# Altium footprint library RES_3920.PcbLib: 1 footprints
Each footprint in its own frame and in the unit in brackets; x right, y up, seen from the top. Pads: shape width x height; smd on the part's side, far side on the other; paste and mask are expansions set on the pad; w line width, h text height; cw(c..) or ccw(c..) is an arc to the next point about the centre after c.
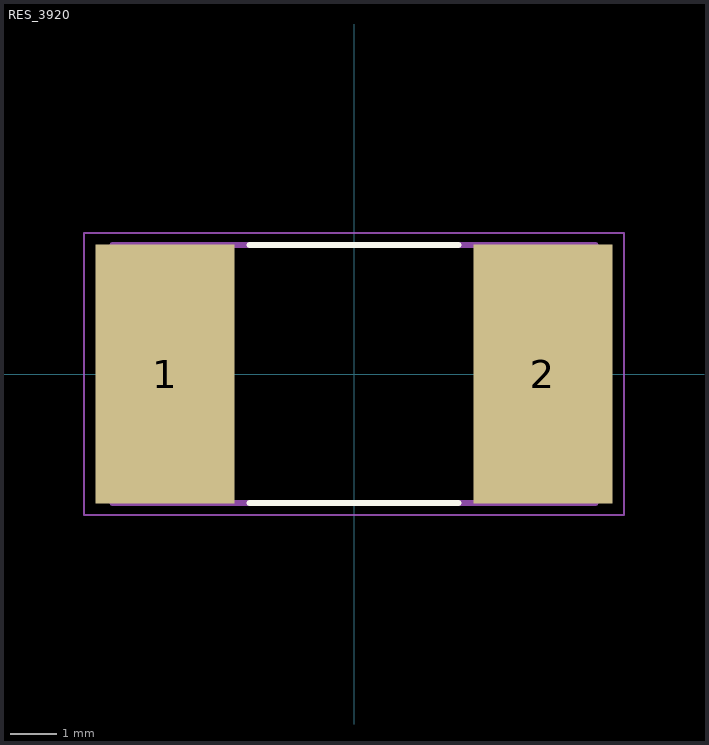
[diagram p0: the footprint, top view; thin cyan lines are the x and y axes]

## RES_3920 [mm]
pads (2):
  rect 2.96x5.51 smd: 1(-4.027,0) 2(4.027,0)
Top Overlay:
  lines w0.127: -2.23,-2.75 2.23,-2.75 ; -2.23,2.75 2.23,2.75
Assembly Top:
  lines w0.127: -5.15,-2.75 -5.15,2.75 5.15,2.75 5.15,-2.75 -5.15,-2.75
Courtyard Top:
  lines w0.05: -5.755,-3.005 -5.755,3.005 5.755,3.005 5.755,-3.005 -5.755,-3.005
3D body "RES_3920.STEP": height 1.05, standoff 0, extent -5.013,-2.591 4.987,2.609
